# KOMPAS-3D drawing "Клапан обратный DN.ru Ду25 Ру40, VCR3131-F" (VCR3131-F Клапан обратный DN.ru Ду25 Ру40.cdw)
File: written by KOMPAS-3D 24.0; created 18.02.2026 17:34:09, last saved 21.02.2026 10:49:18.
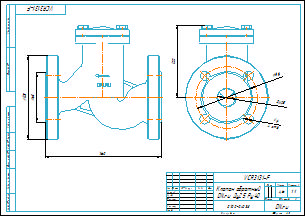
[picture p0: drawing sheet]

Document properties: Автор: R2D2; Форматы листов документа: A3; Полное имя файла: VCR3131-F Клапан обратный DN.ru Ду25 Ру40.m3d; Масса: 4.6; Наименование: Клапан обратный DN.ru Ду25 Ру40; Количество листов документа: 1; Комментарий: D100-04038; Примечание: D100-04038

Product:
- Body: Тело 2  | qty 1
    Масса: 5.543611
- Part/product: Клапан обратный DN.ru Ду25 Ру40  | designation VCR3131-F
    Масса: 4.6
    Форматы листов документа: A3
    Комментарий: D100-04038
    Примечание: D100-04038

Views: Вид 1, Спереди, Проекционный вид 2
Referenced files in E:\Работа\Зайцев\VCR3131-F Клапан обратный DN.ru Ду15-300\DN25\: VCR3131-F Клапан обратный DN.ru Ду25 Ру40.m3d
Referenced files in E:\Работа\Зайцев\Для компаса\: чертеж DN.ru А3.cdt
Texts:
  VCR3131-F
  чертеж DN.ru А3.cdt
  Клапан обратный
  DN.ru Ду25 Ру40
  Клапан обратный DN.ru Ду25 Ру40
  VCR3131-F Клапан обратный DN.ru Ду25 Ру40
Dimensions and other numbers on the sheet: 0; 3; 2; 4; 85; 14; 4 отв.; 25; 100; 160; 68; 115; 1:1; 1; 4,6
